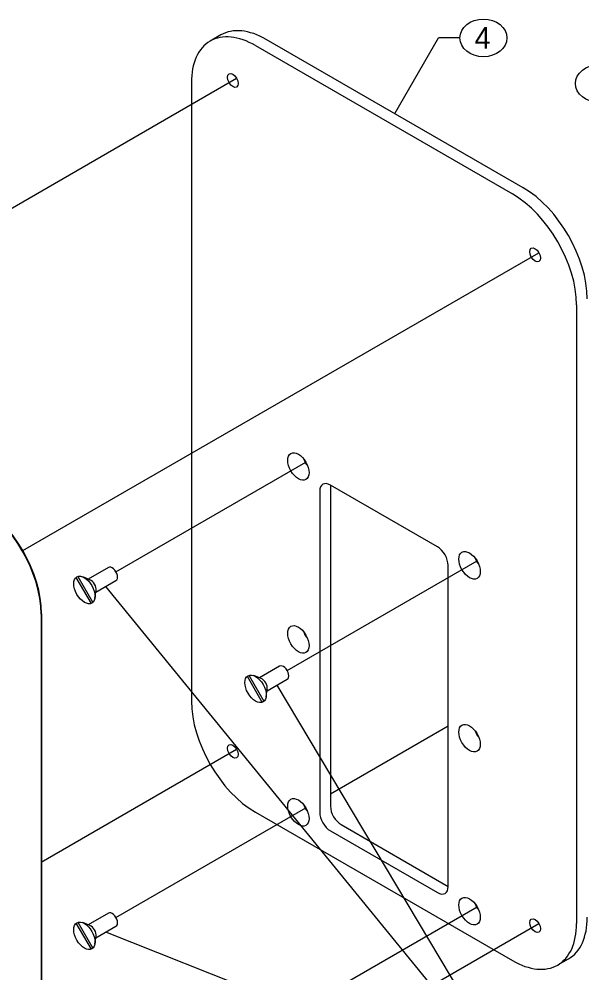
# Model space of a CAD drawing. Extents: x 99862 to 103151, y 100000 to 105076.
# Drawn here: x 100935 to 101353, y 100408 to 101118 of the extents above; entities that cross this region are included whole.
import ezdxf

# ---------------------------------------------------------------- set-up
doc = ezdxf.new("R2010")
doc.units = 0
for name, color, linetype in [('Level 15', 7, 'Continuous'), ('Level 16', 7, 'Continuous'), ('Level 20', 7, 'Continuous'), ('Level 40', 7, 'Continuous'), ('Level 41', 7, 'Continuous')]:
    doc.layers.add(name, color=color, linetype=linetype)

msp = doc.modelspace()

# ---------------------------------------------------------------- linework, layer by layer
at = {"layer": 'Level 15'}
for p, q in [((101214.28, 101047.6), (101246.78, 101103.89)), ((101262.78, 101103.89), (101246.78, 101103.89)), ((101309.8, 100315.62), (100999.58, 100695.96)), ((101309.8, 100315.62), (101126.86, 100622.47)), ((101309.8, 100315.62), (100999.58, 100438.76))]:
    msp.add_line(p, q, dxfattribs=at)
at = {"layer": 'Level 16'}
for p, q in [((100726.7, 100860.18), (101096.8, 101073.86)), ((100937.79, 100722.62), (101321.47, 100944.14)), ((101007.08, 100706.78), (101148.31, 100788.32)), ((101134.36, 100633.3), (101275.59, 100714.83)), ((101166.55, 100541.65), (101254.05, 100592.17)), ((100951.37, 100490.9), (101096.8, 100574.87)), ((101007.08, 100449.58), (101148.31, 100531.12)), ((101134.36, 100376.1), (101275.59, 100457.64)), ((100951.77, 100231.71), (101321.47, 100445.16))]:
    msp.add_line(p, q, dxfattribs=at)
at = {"layer": 'Level 20'}
for centre in [(101280.28, 101103.89), (101366.2, 101069.95)]:
    msp.add_ellipse(centre, major_axis=(-17.5, 0), ratio=0.8, dxfattribs=at)
at = {"layer": 'Level 40'}
for p, q in [((100951.37, 100675.35), (100951.37, 100215.34)), ((100951.77, 100675.58), (100951.77, 100215.57))]:
    msp.add_line(p, q, dxfattribs=at)
for centre in [(100903.64, 100702.91), (100904.04, 100703.14)]:
    msp.add_ellipse(centre, major_axis=(-33.75, 58.46), ratio=0.57735, start_param=3.926991, end_param=5.497787, dxfattribs=at)
at = {"layer": 'Level 41'}
for p, q in [((101085.07, 101106.05), (101077.12, 101101.46)), ((101309.74, 100992.48), (101118.82, 101102.71)), ((101110.87, 101098.12), (101301.78, 100987.89)), ((101063.14, 101070.56), (101063.14, 100610.55)), ((101349.51, 100905.22), (101349.51, 100445.21)), ((101158.6, 100766.7), (101158.6, 100527.88)), ((101166.55, 100771.29), (101166.55, 100532.47)), ((101246.1, 100725.37), (101166.55, 100771.29)), ((101001.46, 100710.03), (100986.46, 100701.37)), ((101254.05, 100472.76), (101254.05, 100711.59)), ((100977.35, 100702.52), (100988.52, 100683.16)), ((100978.65, 100703.27), (100989.82, 100683.91)), ((100987.74, 100700.86), (100982.36, 100703)), ((100992.09, 100691.63), (101007.08, 100700.29)), ((100991.45, 100687.26), (100992.29, 100692.99)), ((101128.74, 100636.54), (101113.74, 100627.89)), ((101104.63, 100629.03), (101115.8, 100609.68)), ((101105.93, 100629.78), (101117.1, 100610.43)), ((101115.02, 100627.38), (101109.64, 100629.52)), ((101119.37, 100618.14), (101134.36, 100626.8)), ((101118.72, 100613.77), (101119.57, 100619.51)), ((101110.87, 100527.88), (101301.78, 100417.65)), ((101174.5, 100518.69), (101254.05, 100472.76)), ((101166.55, 100514.1), (101246.1, 100468.17)), ((101001.46, 100452.83), (100986.46, 100444.18)), ((100977.35, 100445.32), (100988.52, 100425.97)), ((100978.65, 100446.07), (100989.82, 100426.72)), ((100987.74, 100443.67), (100982.36, 100445.8)), ((100992.09, 100434.43), (101007.08, 100443.09)), ((100991.45, 100430.06), (100992.29, 100435.8)), ((101335.59, 100414.34), (101343.49, 100418.9)), ((101335.53, 100414.31), (101335.59, 100414.34))]:
    msp.add_line(p, q, dxfattribs=at)
for centre, major_axis, start_param, end_param in [((101118.82, 101047.6), (-33.75, 58.46), 5.497787, 6.283185), ((101110.87, 101043), (-33.75, 58.46), 6.283185, 7.068583), ((101110.87, 101043), (-33.75, 58.46), 5.497787, 6.283185), ((101301.78, 100932.78), (-33.75, 58.46), 3.926991, 5.497787), ((101309.74, 100937.37), (-33.75, 58.46), 3.926991, 5.497787), ((101150.64, 100789.66), (-2.81, 4.87), 1.084101, 2.057491), ((101166.55, 100762.11), (-5.63, 9.74), 5.497787, 7.068583), ((101246.1, 100716.18), (-5.63, 9.74), 3.926991, 5.497787), ((101277.92, 100716.18), (-2.81, 4.87), 1.084101, 2.057491), ((101004.27, 100705.16), (2.81, -4.87), 6.28318, 9.424778), ((101004.27, 100705.16), (2.81, -4.87), 3.141593, 3.141605), ((100988.36, 100695.97), (2.81, -4.87), 0.630137, 2.511455), ((101150.64, 100661.07), (-2.81, 4.87), 1.084101, 2.057491), ((101131.55, 100631.67), (2.81, -4.87), 6.28318, 9.424778), ((101131.55, 100631.67), (2.81, -4.87), 3.141593, 3.141605), ((101115.64, 100622.49), (2.81, -4.87), 0.630137, 2.511453), ((101110.87, 100582.99), (33.75, -58.46), 3.926991, 5.497787), ((101277.92, 100587.58), (-2.81, 4.87), 1.084101, 2.057491), ((101150.64, 100532.47), (-2.81, 4.87), 1.084101, 2.057491), ((101174.5, 100527.88), (-5.63, 9.74), 0.785398, 2.356194), ((101166.55, 100523.28), (-5.63, 9.74), 0.785398, 2.356194), ((101246.1, 100477.35), (-5.63, 9.74), 2.356194, 3.926991), ((101277.92, 100458.98), (-2.81, 4.87), 1.084101, 2.057491), ((101004.27, 100447.96), (2.81, -4.87), 6.28318, 9.424778), ((101004.27, 100447.96), (2.81, -4.87), 3.141593, 3.141605), ((101309.74, 100477.35), (33.75, -58.46), 0, 0.785398), ((100988.36, 100438.78), (2.81, -4.87), 0.630137, 2.511455), ((101301.78, 100472.76), (33.75, -58.46), 6.283185, 7.068583), ((101301.78, 100472.76), (33.75, -58.46), 5.497787, 6.283185)]:
    msp.add_ellipse(centre, major_axis=major_axis, ratio=0.57735, start_param=start_param, end_param=end_param, dxfattribs=at)
for centre, major_axis in [((101093.99, 101072.23), (-2.81, 4.87)), ((101318.66, 100942.52), (-2.81, 4.87)), ((101142.69, 100785.07), (-5.63, 9.74)), ((101269.96, 100711.59), (-5.63, 9.74)), ((100983.59, 100693.22), (-5.63, 9.74)), ((101142.69, 100656.47), (-5.63, 9.74)), ((101110.87, 100619.73), (-5.63, 9.74)), ((101269.96, 100582.99), (-5.63, 9.74)), ((101093.99, 100573.25), (-2.81, 4.87)), ((101142.69, 100527.88), (-5.63, 9.74)), ((101269.96, 100454.39), (-5.63, 9.74)), ((100983.59, 100436.02), (-5.63, 9.74)), ((101318.66, 100443.53), (-2.81, 4.87))]:
    msp.add_ellipse(centre, major_axis=major_axis, ratio=0.57735, dxfattribs=at)

# ---------------------------------------------------------------- texts
at = {"layer": 'Level 20'}
msp.add_text('4', height=16, dxfattribs=at).set_placement((101273.68, 101095.89))

doc.saveas('drawing.dxf')
